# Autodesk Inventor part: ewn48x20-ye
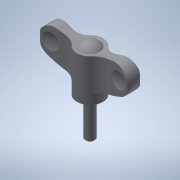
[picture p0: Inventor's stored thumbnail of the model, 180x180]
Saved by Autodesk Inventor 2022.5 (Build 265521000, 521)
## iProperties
Created: 2016-12
Part Number: ewn48x20-ye
Material: 一般
Document SubType Name: Modeling
Designer: imaocorp
Density: 1 g/cm^3
Appearance: 既定
Author: imaocorp
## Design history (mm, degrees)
node "ewn48x20-ye.x_t1"
node "ewn48x20-ye"
node "Base1"
